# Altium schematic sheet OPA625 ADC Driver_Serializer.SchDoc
size 431 x 279 mm; Date: Not shown in title block; ApprovedBy: Not shown in title block; CheckedBy: Not shown in title block; Author: Not shown in title block; CompanyName: Not shown in title block; Engineer: Not shown in title block; Organization: Not shown in title block; Address1: Not shown in title block; Address2: Not shown in title block; Address3: Not shown in title block; Address4: Not shown in title block; DocumentNumber: 4; Revision: Use project parameter SCH_Rev; SheetNumber: 4; SheetTotal: 8; PageSetup: Record=PageOptions¦CenterHorizontal=True¦CenterVertical=True¦PrintScale=1.00¦XCorrection=1.00¦YCorrection=1.00¦PrintKind=0¦BorderSize=5000000¦LeftOffset=0¦BottomOffset=0¦Orientation=2¦PaperLength=1000¦PaperWidth=1000¦Scale=100¦PaperSource=15¦PrintQuality=600¦MediaType=1¦DitherType=10¦PaperKind=Letter¦PrintScaleMode=1
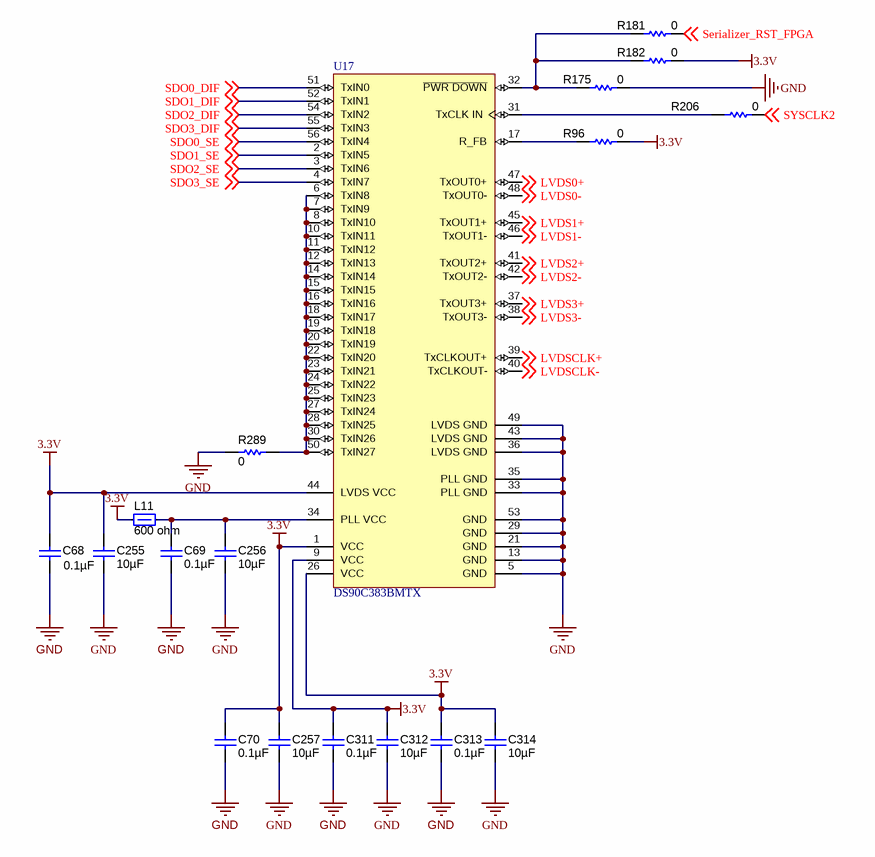
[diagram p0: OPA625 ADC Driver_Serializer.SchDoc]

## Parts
C68  ValueDisplayed: 0.1µF  [0603]  (hidden comment: C0603C104J3RACTU)
C69  ValueDisplayed: 0.1µF  [0603]  (hidden comment: C0603C104J3RACTU)
C70  ValueDisplayed: 0.1µF  [0603]  (hidden comment: C0603C104J3RACTU)
C255  ValueDisplayed: 10µF  [0805_HV]  (hidden comment: GRM21BR71A106KE51L)
C256  ValueDisplayed: 10µF  [0805_HV]  (hidden comment: GRM21BR71A106KE51L)
C257  ValueDisplayed: 10µF  [0805_HV]  (hidden comment: GRM21BR71A106KE51L)
C311  ValueDisplayed: 0.1µF  [0603]  (hidden comment: C0603C104J3RACTU)
C312  ValueDisplayed: 10µF  [0805_HV]  (hidden comment: GRM21BR71A106KE51L)
C313  ValueDisplayed: 0.1µF  [0603]  (hidden comment: C0603C104J3RACTU)
C314  ValueDisplayed: 10µF  [0805_HV]  (hidden comment: GRM21BR71A106KE51L)
L11  value 600 ohm  [0805_HV]  (hidden comment: MPZ2012S601A)
R96  ValueDisplayed: 0  [0402]  (hidden comment: ERJ-2GE0R00X)
R175  ValueDisplayed: 0  [0402]  (hidden comment: ERJ-2GE0R00X)
R181  ValueDisplayed: 0  [0402]  (hidden comment: ERJ-2GE0R00X)
R182  ValueDisplayed: 0  [0402]  (hidden comment: ERJ-2GE0R00X)
R206  ValueDisplayed: 0  [0402]  (hidden comment: ERJ-2GE0R00X)
R289  ValueDisplayed: 0  [0402]  (hidden comment: ERJ-2GE0R00X)
U17  DS90C383BMTX  [MTD56_N]

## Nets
3.3V: C68.1 C70.1 C255.1 C257.1 C311.1 C312.1 C313.1 C314.1 L11.2 R96.2 R182.2 U17.1(VCC) U17.9(VCC) U17.26(VCC) U17.44(LVDS_VCC)
GND: C68.2 C69.2 C70.2 C255.2 C256.2 C257.2 C311.2 C312.2 C313.2 C314.2 R175.2 R289.2 U17.5(GND) U17.13(GND) U17.21(GND) U17.29(GND) U17.33(PLL_GND) U17.35(PLL_GND) U17.36(LVDS_GND) U17.43(LVDS_GND) U17.49(LVDS_GND) U17.53(GND)
LVDS0+: U17.47(TxOUT0+) ; off-sheet LVDS0+
LVDS0-: U17.48(TxOUT0-) ; off-sheet LVDS0-
LVDS1+: U17.45(TxOUT1+) ; off-sheet LVDS1+
LVDS1-: U17.46(TxOUT1-) ; off-sheet LVDS1-
LVDS2+: U17.41(TxOUT2+) ; off-sheet LVDS2+
LVDS2-: U17.42(TxOUT2-) ; off-sheet LVDS2-
LVDS3+: U17.37(TxOUT3+) ; off-sheet LVDS3+
LVDS3-: U17.38(TxOUT3-) ; off-sheet LVDS3-
LVDSCLK+: U17.39(TxCLKOUT+) ; off-sheet LVDSCLK+
LVDSCLK-: U17.40(TxCLKOUT-) ; off-sheet LVDSCLK-
SDO0_DIF: U17.51(TxIN0) ; off-sheet SDO0_DIF
SDO0_SE: U17.56(TxIN4) ; off-sheet SDO0_SE
SDO1_DIF: U17.52(TxIN1) ; off-sheet SDO1_DIF
SDO1_SE: U17.2(TxIN5) ; off-sheet SDO1_SE
SDO2_DIF: U17.54(TxIN2) ; off-sheet SDO2_DIF
SDO2_SE: U17.3(TxIN6) ; off-sheet SDO2_SE
SDO3_DIF: U17.55(TxIN3) ; off-sheet SDO3_DIF
SDO3_SE: U17.4(TxIN7) ; off-sheet SDO3_SE
Serializer_RST_FPGA: R181.2 ; off-sheet Serializer_RST_FPGA
SYSCLK2: R206.2 ; off-sheet SYSCLK2
NetC69_1: C69.1 C256.1 L11.1 U17.34(PLL_VCC)
NetR96_1: R96.1 U17.17(R_FB)
NetR175_1: R175.1 R181.1 R182.1 U17.32(~{PWR_DOWN})
NetR206_1: R206.1 U17.31(TxCLK_IN)
NetR289_1: R289.1 U17.6(TxIN8) U17.7(TxIN9) U17.8(TxIN10) U17.10(TxIN11) U17.11(TxIN12) U17.12(TxIN13) U17.14(TxIN14) U17.15(TxIN15) U17.16(TxIN16) U17.18(TxIN17) U17.19(TxIN18) U17.20(TxIN19) U17.22(TxIN20) U17.23(TxIN21) U17.24(TxIN22) U17.25(TxIN23) U17.27(TxIN24) U17.28(TxIN25) U17.30(TxIN26) U17.50(TxIN27)

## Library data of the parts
C68-C70 C311 C313 = C0603C104J3RACTU: CAP, CERM, 0.1 µF, 25 V, +/- 5%, X7R, 0603; Manufacturer: Kemet; Polarized: N; CompType: Capacitor; Value: 0.1uF; U/M: EA; Cap_F: 0.0000001; Tolerance_%: 5; Value1: Unknown; VDC_V: 25; Value2: 25V; TaMin_C: -55; TaMax_C: 125
C255-C257 C312 C314 = GRM21BR71A106KE51L: CAP, CERM, 10 µF, 10 V, +/- 10%, X7R, 0805; Manufacturer: MuRata; Polarized: N; CompType: Capacitor; Value: 10uF; U/M: EA; Cap_F: 0.00001; Tolerance_%: 10; ESR_ohm: 0.003; Value1: 0.003 ohm; Value2: 10V; TaMin_C: -55; TaMax_C: 125; Cap_Case: 0805; AEC Category: Q200
L11 = MPZ2012S601A: Ferrite Bead, 600 ohm @ 100MHz, 2A, 0805; Manufacturer: TDK; Imax_A: 2; DCR_ohm: 0.1; Value1: 0.1 ohm; ZTyp@100MHz_Ohm: 600
R96 R175 R181 R182 R206 R289 = ERJ-2GE0R00X: RES, 0, 5%, 0.063 W, 0402; Manufacturer: Panasonic; CompType: Resistor; Value: 0; Value_Code: 0000; Tolerance_%: 5; Power_W: 0.063; Value2: 0.063W; VDC_V: 50; TempCo: 600 ppm/C; EIA_Code: E24; U/M: EA; AEC Category: Q200
U17 = DS90C383BMTX: +3.3V Programmable LVDS Transmitter 24-Bit Flat Panel Display (FPD) Link - 65 MHz, 56-pin TSSOP; Manufacturer: Texas Instruments; PackageTopMarking: NSUZXYTTE#*DS90C383BMT; PowerWise: N; CompType: Interface IC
